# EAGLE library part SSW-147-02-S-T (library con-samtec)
THROUGH-HOLE .025" SQ POST SOCKET Source: Samtec SSW.pdf
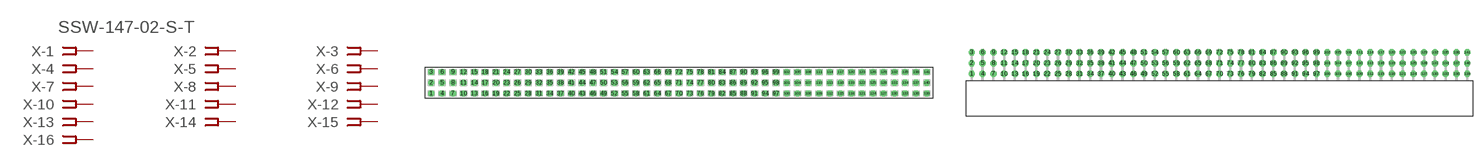
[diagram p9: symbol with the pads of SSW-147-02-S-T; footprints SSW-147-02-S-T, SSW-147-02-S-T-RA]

Designator prefix X; gates -1=FPINV -2=FPIN -3=FPIN -4=FPIN -5=FPIN -6=FPIN -7=FPIN -8=FPIN -9=FPIN -10=FPIN -11=FPIN -12=FPIN -13=FPIN -14=FPIN -15=FPIN -16=FPIN -17=FPIN -18=FPIN -19=FPIN -20=FPIN -21=FPIN -22=FPIN -23=FPIN -24=FPIN -25=FPIN -26=FPIN -27=FPIN -28=FPIN -29=FPIN -30=FPIN -31=FPIN -32=FPIN -33=FPIN -34=FPIN -35=FPIN -36=FPIN -37=FPIN -38=FPIN -39=FPIN -40=FPIN -41=FPIN -42=FPIN -43=FPIN -44=FPIN -45=FPIN -46=FPIN -47=FPIN -48=FPIN -49=FPIN -50=FPIN -51=FPIN -52=FPIN -53=FPIN -54=FPIN -55=FPIN -56=FPIN -57=FPIN -58=FPIN -59=FPIN -60=FPIN -61=FPIN -62=FPIN -63=FPIN -64=FPIN -65=FPIN -66=FPIN -67=FPIN -68=FPIN -69=FPIN -70=FPIN -71=FPIN -72=FPIN -73=FPIN -74=FPIN -75=FPIN -76=FPIN -77=FPIN -78=FPIN -79=FPIN -80=FPIN -81=FPIN -82=FPIN -83=FPIN -84=FPIN -85=FPIN -86=FPIN -87=FPIN -88=FPIN -89=FPIN -90=FPIN -91=FPIN -92=FPIN -93=FPIN -94=FPIN -95=FPIN -96=FPIN -97=FPIN -98=FPIN -99=FPIN -100=FPIN -101=FPIN -102=FPIN -103=FPIN -104=FPIN -105=FPIN -106=FPIN -107=FPIN -108=FPIN -109=FPIN -110=FPIN -111=FPIN -112=FPIN -113=FPIN -114=FPIN -115=FPIN -116=FPIN -117=FPIN -118=FPIN -119=FPIN -120=FPIN -121=FPIN -122=FPIN -123=FPIN -124=FPIN -125=FPIN -126=FPIN -127=FPIN -128=FPIN -129=FPIN -130=FPIN -131=FPIN -132=FPIN -133=FPIN -134=FPIN -135=FPIN -136=FPIN -137=FPIN -138=FPIN -139=FPIN -140=FPIN -141=FPIN

## SSW-147-02-S-T (OC_FARNELL: unknown; OC_NEWARK: unknown)  [SSW-147-02-S-T]
1  -1:1  pas
2  -2:1  pas
3  -3:1  pas
4  -4:1  pas
5  -5:1  pas
6  -6:1  pas
7  -7:1  pas
8  -8:1  pas
9  -9:1  pas
10  -10:1  pas
11  -11:1  pas
12  -12:1  pas
13  -13:1  pas
14  -14:1  pas
15  -15:1  pas
16  -16:1  pas
17  -17:1  pas
18  -18:1  pas
19  -19:1  pas
20  -20:1  pas
21  -21:1  pas
22  -22:1  pas
23  -23:1  pas
24  -24:1  pas
25  -25:1  pas
26  -26:1  pas
27  -27:1  pas
28  -28:1  pas
29  -29:1  pas
30  -30:1  pas
31  -31:1  pas
32  -32:1  pas
33  -33:1  pas
34  -34:1  pas
35  -35:1  pas
36  -36:1  pas
37  -37:1  pas
38  -38:1  pas
39  -39:1  pas
40  -40:1  pas
41  -41:1  pas
42  -42:1  pas
43  -43:1  pas
44  -44:1  pas
45  -45:1  pas
46  -46:1  pas
47  -47:1  pas
48  -48:1  pas
49  -49:1  pas
50  -50:1  pas
51  -51:1  pas
52  -52:1  pas
53  -53:1  pas
54  -54:1  pas
55  -55:1  pas
56  -56:1  pas
57  -57:1  pas
58  -58:1  pas
59  -59:1  pas
60  -60:1  pas
61  -61:1  pas
62  -62:1  pas
63  -63:1  pas
64  -64:1  pas
65  -65:1  pas
66  -66:1  pas
67  -67:1  pas
68  -68:1  pas
69  -69:1  pas
70  -70:1  pas
71  -71:1  pas
72  -72:1  pas
73  -73:1  pas
74  -74:1  pas
75  -75:1  pas
76  -76:1  pas
77  -77:1  pas
78  -78:1  pas
79  -79:1  pas
80  -80:1  pas
81  -81:1  pas
82  -82:1  pas
83  -83:1  pas
84  -84:1  pas
85  -85:1  pas
86  -86:1  pas
87  -87:1  pas
88  -88:1  pas
89  -89:1  pas
90  -90:1  pas
91  -91:1  pas
92  -92:1  pas
93  -93:1  pas
94  -94:1  pas
95  -95:1  pas
96  -96:1  pas
97  -97:1  pas
98  -98:1  pas
99  -99:1  pas
100  -100:1  pas
101  -101:1  pas
102  -102:1  pas
103  -103:1  pas
104  -104:1  pas
105  -105:1  pas
106  -106:1  pas
107  -107:1  pas
108  -108:1  pas
109  -109:1  pas
110  -110:1  pas
111  -111:1  pas
112  -112:1  pas
113  -113:1  pas
114  -114:1  pas
115  -115:1  pas
116  -116:1  pas
117  -117:1  pas
118  -118:1  pas
119  -119:1  pas
120  -120:1  pas
121  -121:1  pas
122  -122:1  pas
123  -123:1  pas
124  -124:1  pas
125  -125:1  pas
126  -126:1  pas
127  -127:1  pas
128  -128:1  pas
129  -129:1  pas
130  -130:1  pas
131  -131:1  pas
132  -132:1  pas
133  -133:1  pas
134  -134:1  pas
135  -135:1  pas
136  -136:1  pas
137  -137:1  pas
138  -138:1  pas
139  -139:1  pas
140  -140:1  pas
141  -141:1  pas

## SSW-147-02-S-TRA (OC_FARNELL: unknown; OC_NEWARK: unknown)  [SSW-147-02-S-T-RA]
Pads as for SSW-147-02-S-T

## Footprint SSW-147-02-S-T (pad centres in mm)
THROUGH-HOLE .025" SQ POST SOCKET Source: Samtec SSW.pdf
drill 1 pad 1.5 octagon: 1 -58.42,-2.54; 2 -58.42,0; 3 -58.42,2.54; 4 -55.88,-2.54; 5 -55.88,0; 6 -55.88,2.54; 7 -53.34,-2.54; 8 -53.34,0; 9 -53.34,2.54; 10 -50.8,-2.54; 11 -50.8,0; 12 -50.8,2.54; 13 -48.26,-2.54; 14 -48.26,0; 15 -48.26,2.54; 16 -45.72,-2.54; 17 -45.72,0; 18 -45.72,2.54; 19 -43.18,-2.54; 20 -43.18,0; 21 -43.18,2.54; 22 -40.64,-2.54; 23 -40.64,0; 24 -40.64,2.54; 25 -38.1,-2.54; 26 -38.1,0; 27 -38.1,2.54; 28 -35.56,-2.54; 29 -35.56,0; 30 -35.56,2.54; 31 -33.02,-2.54; 32 -33.02,0; 33 -33.02,2.54; 34 -30.48,-2.54; 35 -30.48,0; 36 -30.48,2.54; 37 -27.94,-2.54; 38 -27.94,0; 39 -27.94,2.54; 40 -25.4,-2.54; 41 -25.4,0; 42 -25.4,2.54; 43 -22.86,-2.54; 44 -22.86,0; 45 -22.86,2.54; 46 -20.32,-2.54; 47 -20.32,0; 48 -20.32,2.54; 49 -17.78,-2.54; 50 -17.78,0; 51 -17.78,2.54; 52 -15.24,-2.54; 53 -15.24,0; 54 -15.24,2.54; 55 -12.7,-2.54; 56 -12.7,0; 57 -12.7,2.54; 58 -10.16,-2.54; 59 -10.16,0; 60 -10.16,2.54; 61 -7.62,-2.54; 62 -7.62,0; 63 -7.62,2.54; 64 -5.08,-2.54; 65 -5.08,0; 66 -5.08,2.54; 67 -2.54,-2.54; 68 -2.54,0; 69 -2.54,2.54; 70 0,-2.54; 71 0,0; 72 0,2.54; 73 2.54,-2.54; 74 2.54,0; 75 2.54,2.54; 76 5.08,-2.54; 77 5.08,0; 78 5.08,2.54; 79 7.62,-2.54; 80 7.62,0; 81 7.62,2.54; 82 10.16,-2.54; 83 10.16,0; 84 10.16,2.54; 85 12.7,-2.54; 86 12.7,0; 87 12.7,2.54; 88 15.24,-2.54; 89 15.24,0; 90 15.24,2.54; 91 17.78,-2.54; 92 17.78,0; 93 17.78,2.54; 94 20.32,-2.54; 95 20.32,0; 96 20.32,2.54; 97 22.86,-2.54; 98 22.86,0; 99 22.86,2.54; 100 25.4,-2.54; 101 25.4,0; 102 25.4,2.54; 103 27.94,-2.54; 104 27.94,0; 105 27.94,2.54; 106 30.48,-2.54; 107 30.48,0; 108 30.48,2.54; 109 33.02,-2.54; 110 33.02,0; 111 33.02,2.54; 112 35.56,-2.54; 113 35.56,0; 114 35.56,2.54; 115 38.1,-2.54; 116 38.1,0; 117 38.1,2.54; 118 40.64,-2.54; 119 40.64,0; 120 40.64,2.54; 121 43.18,-2.54; 122 43.18,0; 123 43.18,2.54; 124 45.72,-2.54; 125 45.72,0; 126 45.72,2.54; 127 48.26,-2.54; 128 48.26,0; 129 48.26,2.54; 130 50.8,-2.54; 131 50.8,0; 132 50.8,2.54; 133 53.34,-2.54; 134 53.34,0; 135 53.34,2.54; 136 55.88,-2.54; 137 55.88,0; 138 55.88,2.54; 139 58.42,-2.54; 140 58.42,0; 141 58.42,2.54

## Footprint SSW-147-02-S-T-RA (pad centres in mm)
THROUGH-HOLE .025" SQ POST SOCKET Source: Samtec SSW.pdf
drill 1 pad 1.5 octagon: 1 -58.42,1.524; 2 -58.42,4.064; 3 -58.42,6.604; 4 -55.88,1.524; 5 -55.88,4.064; 6 -55.88,6.604; 7 -53.34,1.524; 8 -53.34,4.064; 9 -53.34,6.604; 10 -50.8,1.524; 11 -50.8,4.064; 12 -50.8,6.604; 13 -48.26,1.524; 14 -48.26,4.064; 15 -48.26,6.604; 16 -45.72,1.524; 17 -45.72,4.064; 18 -45.72,6.604; 19 -43.18,1.524; 20 -43.18,4.064; 21 -43.18,6.604; 22 -40.64,1.524; 23 -40.64,4.064; 24 -40.64,6.604; 25 -38.1,1.524; 26 -38.1,4.064; 27 -38.1,6.604; 28 -35.56,1.524; 29 -35.56,4.064; 30 -35.56,6.604; 31 -33.02,1.524; 32 -33.02,4.064; 33 -33.02,6.604; 34 -30.48,1.524; 35 -30.48,4.064; 36 -30.48,6.604; 37 -27.94,1.524; 38 -27.94,4.064; 39 -27.94,6.604; 40 -25.4,1.524; 41 -25.4,4.064; 42 -25.4,6.604; 43 -22.86,1.524; 44 -22.86,4.064; 45 -22.86,6.604; 46 -20.32,1.524; 47 -20.32,4.064; 48 -20.32,6.604; 49 -17.78,1.524; 50 -17.78,4.064; 51 -17.78,6.604; 52 -15.24,1.524; 53 -15.24,4.064; 54 -15.24,6.604; 55 -12.7,1.524; 56 -12.7,4.064; 57 -12.7,6.604; 58 -10.16,1.524; 59 -10.16,4.064; 60 -10.16,6.604; 61 -7.62,1.524; 62 -7.62,4.064; 63 -7.62,6.604; 64 -5.08,1.524; 65 -5.08,4.064; 66 -5.08,6.604; 67 -2.54,1.524; 68 -2.54,4.064; 69 -2.54,6.604; 70 0,1.524; 71 0,4.064; 72 0,6.604; 73 2.54,1.524; 74 2.54,4.064; 75 2.54,6.604; 76 5.08,1.524; 77 5.08,4.064; 78 5.08,6.604; 79 7.62,1.524; 80 7.62,4.064; 81 7.62,6.604; 82 10.16,1.524; 83 10.16,4.064; 84 10.16,6.604; 85 12.7,1.524; 86 12.7,4.064; 87 12.7,6.604; 88 15.24,1.524; 89 15.24,4.064; 90 15.24,6.604; 91 17.78,1.524; 92 17.78,4.064; 93 17.78,6.604; 94 20.32,1.524; 95 20.32,4.064; 96 20.32,6.604; 97 22.86,1.524; 98 22.86,4.064; 99 22.86,6.604; 100 25.4,1.524; 101 25.4,4.064; 102 25.4,6.604; 103 27.94,1.524; 104 27.94,4.064; 105 27.94,6.604; 106 30.48,1.524; 107 30.48,4.064; 108 30.48,6.604; 109 33.02,1.524; 110 33.02,4.064; 111 33.02,6.604; 112 35.56,1.524; 113 35.56,4.064; 114 35.56,6.604; 115 38.1,1.524; 116 38.1,4.064; 117 38.1,6.604; 118 40.64,1.524; 119 40.64,4.064; 120 40.64,6.604; 121 43.18,1.524; 122 43.18,4.064; 123 43.18,6.604; 124 45.72,1.524; 125 45.72,4.064; 126 45.72,6.604; 127 48.26,1.524; 128 48.26,4.064; 129 48.26,6.604; 130 50.8,1.524; 131 50.8,4.064; 132 50.8,6.604; 133 53.34,1.524; 134 53.34,4.064; 135 53.34,6.604; 136 55.88,1.524; 137 55.88,4.064; 138 55.88,6.604; 139 58.42,1.524; 140 58.42,4.064; 141 58.42,6.604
